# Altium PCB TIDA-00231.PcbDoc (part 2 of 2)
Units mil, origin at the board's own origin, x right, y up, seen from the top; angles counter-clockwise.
Board outline 3780 x 2000 mil, 4 copper layers (Top Layer, L2_GND-PLANE, L3_PWR-PLANE, Bottom Layer), stack 90 mil thick; 180 components, 82 nets, 468 pads, 188 vias.
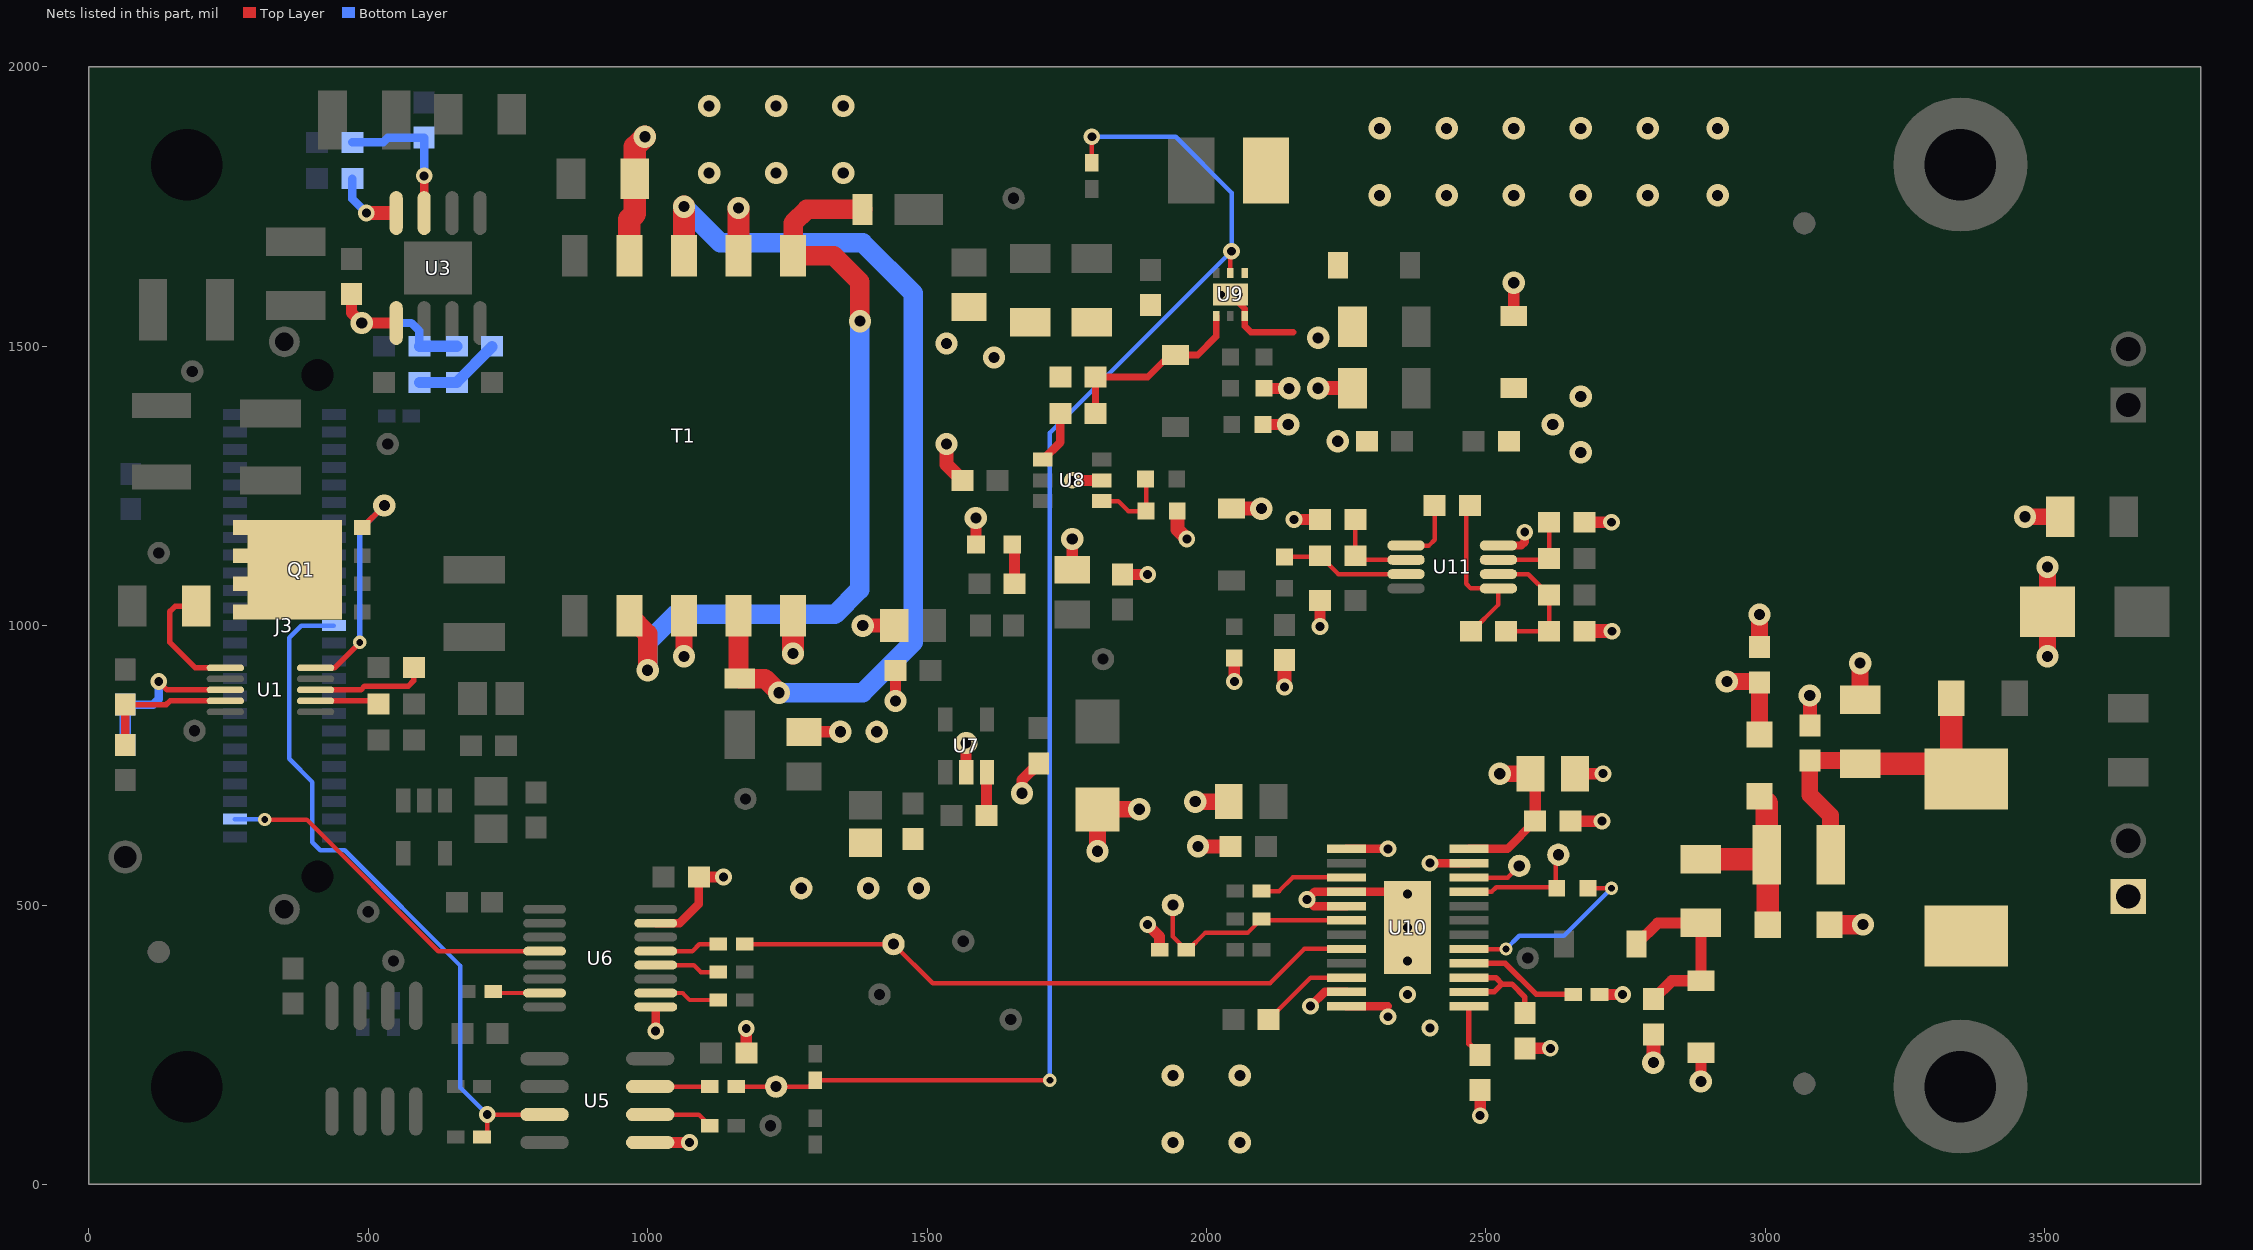
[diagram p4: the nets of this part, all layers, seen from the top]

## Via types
v1: diameter 40, hole 20, Top Layer to Bottom Layer, tented both sides, 92 vias
v2: diameter 30, hole 16, Top Layer to Bottom Layer, tented both sides, 74 vias
v3: diameter 24, hole 12, Top Layer to Bottom Layer, tented both sides, 14 vias
v4: diameter 26, hole 12, Top Layer to Bottom Layer, tented both sides, 4 vias
v5: diameter 25.98, hole 12, Top Layer to Bottom Layer, tented both sides, 4 vias

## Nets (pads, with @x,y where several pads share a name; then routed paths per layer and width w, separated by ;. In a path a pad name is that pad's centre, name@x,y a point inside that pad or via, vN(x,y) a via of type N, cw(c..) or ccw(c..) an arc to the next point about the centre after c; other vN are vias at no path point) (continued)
NetC44_2: C44.2 U10.17 | length 342.4
  Top Layer w8: U10.17@2469.7,421.2 v3(2536.2,421.2) ; C44.2@2683,530 v3(2725,530)
  Bottom Layer w8: v3(2536.2,421.2) 2560,445 2640,445 v3(2725,530)
NetC45_2: C45.2 U10.14 U10.15 | length 208.7
  Top Layer w10: U10.14@2469.7,344.4 2515,344.4 2528.94,358.34 ; U10.15@2469.7,370 2517.88,370 2528.94,358.94 2528.94,358.34 ; C45.2@2570,306.5 2570,335 2546.66,358.34 2528.94,358.34
NetC46_1: C46.1 D9.1 D11.1 R37.2 | length 332.8
  Top Layer w20: D9.1@2770,430 2807.91,467.91 R37.2@2885,467.91 D11.1@2885,364.47 2832.97,364.47 C46.1@2800,331.5
NetC48_1: C48.1 C49.1 D13.1 F1.1 R38.1 | length 595
  Top Layer w30: F1.1@3117.09,590 3117.09,660 3080,697.09 C49.1@3080,758.5 3164.41,758.5 C48.1@3170,752.91
  Top Layer w40: C48.1@3170,752.91 3332.58,752.91 D13.1@3332.91,752.58 ; R38.1@3332.91,870 D13.1@3332.91,752.58 ; D13.1@3360,725.49 D13.1@3332.91,752.58
NetC52_1: C52.1 C53.1 R39.1 | length 156.1
  Bottom Layer w20: C53.1@591.5,1435 R39.1@658.5,1435 ; R39.1@658.5,1436.16 C52.1@721.5,1499.15
NetC52_2: C52.2 R4.2 R41.1 U3.5 | length 324.4
  Top Layer w20: R4.2@470,1593.5 470,1560 v1(488.43,1541.57) ; v1(488.43,1541.57) U3.5@550,1541.57
  Bottom Layer w15: v1(488.43,1541.57) 577.19,1541.57 591.5,1527.27 R41.1@591.5,1500
  Bottom Layer w20: R41.1@591.5,1500 C52.2@658.5,1500
NetC55_1: C55.1 D5.2 R19.1 U9.1 | length 347.8
  Top Layer w12: R19.1@1801.5,1380 C55.1@1801.5,1445 1895,1445 1934.47,1484.47 D5.2@1945,1484.47 1984.47,1484.47 2017.46,1517.46 U9.1@2017.46,1554.3
NetD1_2: D1.2 T1.3 T1.7 | length 1658.6
  Top Layer w20: D1.2@1162.64,907.56 D1.2@1165,905.2
  Top Layer w35: D1.2@1162.64,907.56 T1.7@1162.64,1017.95 ; D1.2@1165,905.2 1209.8,905.2 v1(1235,880)
  Top Layer w40: T1.3@1065,1662.05 v1(1065,1750)
  Bottom Layer w35: v1(1065,1750) 1130,1685 1385,1685 1475,1595 1475,970 1385,880 v1(1235,880)
NetD2_2: D2.2 T1.5 T1.9 | length 1463
  Top Layer w35: T1.9@967.36,1017.95 1000,985.32 v1(1000,920) ; v1(1380,1545) 1380,1615 1332.95,1662.05 T1.5@1260.28,1662.05 1260.28,1720.28 1285,1745 D2.2@1384.8,1745
  Bottom Layer w35: v1(1000,920) 1000,970 1050,1020 1335,1020 1379.5,1064.5 1379.5,1209.5 1380,1210 v1(1380,1545)
NetD3_2: D3.2 R18.1 | length 71.7
  Top Layer w20: D3.2@1652.48,1145 1656.5,1140.98 R18.1@1656.5,1075
NetD7_2: D7.2 L2.2 U9.4
NetD10_1: D10.1 D12.2 F1.2 R37.1 | length 357.2
  Top Layer w40: R37.1@2885,582.09 2995,582.09 F1.2@3002.91,590 ; D12.2@2990,694.88 3002.91,681.97 F1.2@3002.91,590 ; D10.1@3004.88,465 3004.88,588.03 F1.2@3002.91,590
NetQ1_4: Q1.4 U1.10 | length 417.2
  Top Layer w10: U1.10@405.71,924.37 439.37,924.37 v3(485,970) ; Q1.4@489.3,1175.49 v1(528.81,1215)
  Bottom Layer w10: v3(485,970) 485,1171.19 v1(528.81,1215)
NetQ1_5: Q1.5 Q1.6 Q1.7 Q1.8 Q1.9 R3.2 U1.1 | length 224.6
  Top Layer w10: R3.2@192.09,1035 154.68,1035 145,1025.32 145,970 190.63,924.37 U1.1@244.29,924.37
NetR1_1: R1.1 R2.2 U1.4 | length 254.1
  Top Layer w10: R1.1@65,858.5 138.5,858.5 145.32,865.32 U1.4@244.29,865.32
  Top Layer w15: R2.2@65,786.5 R1.1@65,858.5
NetR5_1: R5.1 U1.8 | length 206.1
  Top Layer w10: U1.8@405.71,885 486.73,885 493.43,891.7 571.7,891.7 581.5,901.5 R5.1@581.5,925
NetR6_2: R6.2 U1.7 | length 115
  Top Layer w10: U1.7@405.71,865.32 513.19,865.32 R6.2@518.5,860
NetR9_2: R9.2 U6.7 | length 93
  Top Layer w8: R9.2@723.62,345 726.12,342.5 U6.7@815.59,342.5
NetR10_1: R10.1 U5.7 | length 106.9
  Top Layer w8: U5.7@1004.49,175 R10.1@1111.38,175
NetR11_1: R11.1 U5.6 | length 115.2
  Top Layer w8: U5.6@1004.49,125 1091.38,125 R11.1@1111.38,105
NetR12_1: R12.1 U6.13 | length 117.1
  Top Layer w8: U6.13@1014.41,417.5 1080.13,417.5 1092.63,430 R12.1@1126.38,430
NetR13_1: R13.1 U6.12 | length 117.1
  Top Layer w8: U6.12@1014.41,392.5 1082.5,392.5 1095,380 R13.1@1126.38,380
NetR14_1: R14.1 U6.10 | length 117.1
  Top Layer w8: U6.10@1014.41,342.5 1062.5,342.5 1075,330 R14.1@1126.38,330
NetR17_1: R17.1 U7.3 | length 76
  Top Layer w20: U7.3@1605,735.35 1606.5,733.86 R17.1@1606.5,660
NetR19_2: R19.2 U8.4 | length 95.8
  Top Layer w15: U8.4@1707.5,1297 1738.5,1328 R19.2@1738.5,1380
NetR20_1: R20.1 R21.2 U8.1 | length 144.8
  Top Layer w8: U8.1@1812.5,1223 1842,1223 1860,1205 R21.2@1892,1205 1892,1261.46 R20.1@1891,1262.46
NetR23_1: R23.1 R28.1 TP18.1 U10.6 | length 400.7
  Top Layer w8: TP18.1@1940,500 1940,443.62 R23.1@1963.62,420 1967.56,420 1997.56,450 2073.62,450 R28.1@2098.62,475 2101.12,472.5 U10.6@2250.7,472.5
NetR26_2: R26.2 U10.10 | length 170.3
  Top Layer w8: R26.2@2111.5,295 2186.6,370.1 U10.10@2250.7,370.1
NetR27_1: R27.1 U10.3 | length 162.1
  Top Layer w8: R27.1@2098.62,525 2130,525 2154.3,549.3 U10.3@2250.7,549.3
NetR30_2: R30.2 R32.1 R48.2 U11.2 | length 248.2
  Top Layer w8: U11.2@2522.68,1092.2 2576.3,1092.2 R48.2@2613.5,1055 R30.2@2613.5,990 R32.1@2536.5,990
NetR31_1: R31.1 R36.2 U11.7 | length 230.1
  Top Layer w8: R31.1@2140,1123 2205.5,1123 2236.3,1092.2 U11.7@2357.32,1092.2
NetR32_2: R32.2 R49.1 U11.1 | length 301.7
  Top Layer w8: R49.1@2471.5,1215 2465,1208.5 2465,1075 2473.39,1066.61 U11.1@2522.68,1066.61 2522.68,1037.68 2475,990 R32.2@2473.5,990
NetR33_1: R33.1 U10.13 | length 95.7
  Top Layer w10: U10.13@2469.7,318.8 2469.7,251.8 R33.1@2490,231.5
NetR34_1: R34.1 U10.16 | length 209.7
  Top Layer w10: U10.16@2469.7,395.6 2534.86,395.6 2590.46,340 R34.1@2656.38,340
NetR35_2: R35.2 R36.1 U11.6 | length 158.8
  Top Layer w8: R35.2@2266.5,1190 R36.1@2266.5,1125 2273.7,1117.8 U11.6@2357.32,1117.8
NetR40_2: R40.2 R44.1 U3.3 | length 399.1
  Top Layer w15: U3.3@600,1738.43 v2(600,1805)
  Bottom Layer w15: v2(600,1805) R40.2@600,1873.5 ; 526.5,1865 R44.1@471.5,1865 526.5,1865 ; 526.5,1865 535,1873.5 ; 526.5,1865 535,1873.5 ; 535,1873.5 R40.2@600,1873.5 ; 535,1873.5 R40.2@600,1873.5
NetR45_1: R45.1 U3.4 | length 125.4
  Top Layer w25: v2(496.57,1738.43) U3.4@550,1738.43
  Bottom Layer w15: R45.1@471.5,1800 471.5,1763.5 v2(496.57,1738.43)
NetR46_1: R46.1 R47.2 U1.3 | length 293.2
  Top Layer w10: v2(125,900) 140,885 U1.3@244.29,885
  Bottom Layer w15: R46.1@65,858.5 115,858.5 125,868.5 v2(125,900)
  Bottom Layer w20: R47.2@65,786.5 R46.1@65,858.5
NetR49_2: R49.2 U11.5 | length 116.9
  Top Layer w8: U11.5@2357.32,1143.39 2398.39,1143.39 2408.5,1153.5 R49.2@2408.5,1215
NetR50_2: R50.2 R51.1 U11.3 | length 156.7
  Top Layer w8: U11.3@2522.68,1117.8 2611.3,1117.8 R50.2@2613.5,1120 R51.1@2613.5,1185
NetTP20_1: TP20.1 U10.22 | length 98.9
  Top Layer w8: U10.22@2469.7,549.2 2539.2,549.2 TP20.1@2560,570
PS_EN: R10.2 R15.1 R22.1 TP8.1 U9.5 | length 2666.9
  Top Layer w8: R10.2@1158.62,175 1288.62,175 R15.1@1300,186.38 v3(1720,186.38) ; R22.1@1795,1828.62 v2(1795,1875) ; U9.5@2043.05,1631.07 2043.05,1668.05 v2(2045,1670)
  Bottom Layer w8: v3(1720,186.38) 1720,1345 v2(2045,1670) 2045,1775 1945,1875 v2(1795,1875)
RCLK: J3.26 R8.1 U5.3 | length 1261.4
  Top Layer w8: R8.1@703.62,85 713,94.38 v2(713,125) U5.3@815.51,125
  Bottom Layer w8: J3.26@438.58,1000 380,1000 358.47,978.47 358.47,761.53 400,720 400,612.16 414.08,598.08 457.92,598.08 665,391 665,173 v2(713,125)
SCLK: J3.3 U6.4 | length 651.9
  Top Layer w8: v3(315,653) 390,653 625.5,417.5 U6.4@815.59,417.5
  Bottom Layer w8: J3.3@261.42,653.54 314.46,653.54 v3(315,653)
SCLK_ISO: R12.2 TP13.1 U10.8 | length 1131.5
  Top Layer w8: R12.2@1173.62,430 TP13.1@1440,430 1510,360 2114,360 2175.3,421.3 U10.8@2250.7,421.3
SGND: C17.2 C18.2 C19.2 C20.2 C21.1 C22.2 C23.2 C24.2 C25.2 C26.2 C27.2 C28.2 C29.2 C30.2 C31.2 C32.2 C33.1 C34.1 C35.2 C36.2 C37.2 C38.2 C39.2 C40.2 C41.2 C42.1 C43.2 C45.1 C46.2 C47.2 C48.2 C49.2 C50.1 C55.2 D3.1 D4.2 D6.2 D8.2 D10.2 D11.2 D13.2 D14.1 J2.1 R21.1 R23.2 R24.1 R30.1 R33.2 R34.2 R35.1 R51.2 T1.2 T1.4 T1.6 T1.8 TP11.1 TP14.1 U5.5 U6.9 U6.15 U7.2 U8.2 U9.3 U9.7 U10.1 U10.4 U10.5 U10.11 U10.12 U10.23 U10.25 U11.4 | length 3926.3
  Top Layer w12: U9.7@2043.05,1592.68 2068.64,1567.09 U9.3@2068.64,1554.3 2068.64,1536.36 2080,1525 2155,1525
  Top Layer w15: v2(1014.41,274.41) U6.9@1014.41,317.5 ; U6.15@1014.41,467.5 1057.5,467.5 1091.5,501.5 C18.2@1091.5,550 ; v2(2186.2,318.9) 2211.8,344.5 U10.11@2250.7,344.5 ; U10.12@2250.7,318.9 2325,318.9 ; U10.5@2250.7,498.1 2191.9,498.1 v2(2180,510) 2193.7,523.7 U10.4@2250.7,523.7 2346.3,523.7 2360,510 v2(2360,459.9) ; U10.1@2250.7,600.5 v2(2325,600.5) ; v2(2400,574.8) U10.23@2469.7,574.8 ; U11.4@2522.68,1143.39 2563.39,1143.39 2569.82,1149.82 v2(2569.82,1167.32)
  Top Layer w20: U5.5@1004.49,75 v2(1075,75) ; C18.2@1091.5,550 v2(1136,550) ; C19.2@1176.5,235 v2(1176.5,279) ; C21.1@1280,810 v1(1345,810) ; v1(1443.5,865) C24.2@1443.5,920 ; U7.2@1570,737.76 v1(1570,790) ; D3.1@1587.52,1145 v1(1587.52,1192.52) ; v1(1670,700) 1670,723.5 C29.2@1700,753.5 ; C30.2@1760,1100 v1(1760,1155) ; v2(1760,1260) U8.2@1812.5,1260 ; C32.2@1850,1091.5 v2(1895,1091.5) ; v2(1895,465) 1916.38,443.62 R23.2@1916.38,420 ; v2(2050,900) R24.1@2050,942 ; C35.2@2101.54,1360 v1(2146.54,1360) ; C36.2@2103.05,1424.68 v1(2148.05,1424.68) ; v2(2157.01,1190) R35.1@2203.5,1190 ; v2(2203.5,998.5) C38.2@2203.5,1045 ; v2(2490,123) R33.2@2490,168.5 ; D8.2@2550,1554.47 v1(2550,1613.54) ; C45.1@2570,243.5 v2(2615.5,243.5) ; C43.2@2651.5,650 v2(2708,650) ; C42.1@2660,735 v2(2710,735) ; R51.2@2676.5,1185 v2(2725,1185) ; R34.2@2703.62,340 v2(2745,340) ; v1(2885,184.04) D11.2@2885,235.53
  Top Layer w25: v1(1385,1000) C23.2@1441.54,1000 ; v1(1535,1325) 1535,1288.5 C26.2@1563.5,1260 ; R21.1@1948,1205 1948,1172 v2(1965,1155) ; v1(1985,605) C34.1@2043.5,605 ; D6.2@2045,1209.47 v1(2098.5,1209.47) ; v2(2140,890) C37.2@2140,938.5 ; v1(2200,1425) C40.2@2261.46,1425 ; R30.1@2676.5,990 v2(2726,990) ; v1(2800,217.97) C46.2@2800,268.5 ; C49.2@3080,821.5 v1(3080,875)
  Top Layer w30: v1(1065,945) T1.8@1065,1017.95 ; v1(1805,596.26) D4.2@1805,671.26 v1(1880,671.26) ; v1(1980,685) C33.1@2040,685 ; C47.2@2990,961.5 v1(2990,1020) ; C48.2@3170,867.09 v1(3170,932.91) ; v1(3465,1195) C50.1@3527.91,1195 ; v1(3505.35,945) D14.1@3505.35,1025 v1(3505.35,1105)
  Top Layer w35: D10.2@3115.12,465 v1(3175.12,465)
  Top Layer w40: T1.2@967.36,1662.05 967.36,1727.36 977.09,1737.09 C17.2@977.09,1800 977.09,1857.09 v1(995,1875) ; T1.4@1162.64,1662.05 v1(1162.64,1747.36) ; v1(1260.28,950) T1.6@1260.28,1017.95
  other v1: 1940,75 2060,75 1940,195 2060,195 1395,530 1485,530 2235,1330 1620,1480 1535,1505 2200,1515 2310,1770 2430,1770 2550,1770 2670,1770 2790,1770 2915,1770 1110,1810 1230,1810 1350,1810 2310,1890 2430,1890 2550,1890 2670,1890 2790,1890 2915,1890 1110,1930 1230,1930 1350,1930
  other v2: 2400.3,280 2325,300 2360,339.7 2360,399.8 2360,520
  other v3: 2027.3,1592.68 2058.8,1592.68
VBOOST_OUT: C42.2 C43.1 C47.1 D8.1 D12.1 FB2.2 U10.24 | length 416.2
  Top Layer w15: U10.24@2469.7,600.5 2539,600.5 C43.1@2588.5,650
  Top Layer w20: C42.2@2580,735 2588.5,726.5 C43.1@2588.5,650
  Top Layer w30: v1(2525,735) C42.2@2580,735 ; v1(2931.5,900) C47.1@2980,900 ; D12.1@2990,813.62 C47.1@2990,898.5
  other v1: 2670,1310 2620,1360 2670,1410
VOUT0_0: C44.1 TP22.1 U10.21 | length 218.9
  Top Layer w8: U10.21@2469.7,523.6 2510.4,523.6 2518.8,532 2625,532 2625,585 TP22.1@2630,590
pads on no net: FID1.1 FID2.1 FID3.1 FID4.1 FID5.1 FID6.1 H1.1 H2.1 J3.8 J3.9 J3.13 J3.14 J3.15 J3.17 J3.18 J3.19 J3.20 J3.21 J3.22 J3.23 J3.24 J3.25 J3.27 J3.28 J3.29 J3.30 J3.31 J3.32 J3.33 J3.34 J3.43 J3.44 J3.45 J3.46 J3.47 J3.48 J3.49 J3.MH1 J3.MH2 J3.MH3 J3.MH4 MH1.1 MH2.1 U4.3 U4.4
copper on no net: | length 4560
  Top Layer w8: 3600,140 3700,140 ; 3600,220 3700,220 ; 3600,300 3700,300 ; 3600,60 3600,380 3700,380 3700,60 3600,60
  L2_GND-PLANE w8: 3600,140 3700,140 ; 3600,220 3700,220 ; 3600,300 3700,300 ; 3600,60 3700,60 3700,380 3600,380 3600,60
  L3_PWR-PLANE w8: 3600,140 3700,140 ; 3600,220 3700,220 ; 3600,300 3700,300 ; 3600,60 3600,380 3700,380 3700,60 3600,60
  Bottom Layer w8: 3600,140 3700,140 ; 3600,220 3700,220 ; 3600,300 3700,300 ; 3600,60 3600,380 3700,380 3700,60 3600,60

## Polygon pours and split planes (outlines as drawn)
9.3V_NON_ISO on Bottom Layer "Top Layer-No Net" (hatched 90Degree grid 5 track 8, remove dead copper, pour order 61): 680,800 620,800 605,815 605,1020 585,1040 585,1215 495,1305 495,1370 505,1380 540,1380 545,1375 545,1340 645,1240 645,1035 690,990 690,810
GND on Bottom Layer "Top Layer-No Net" (hatched 90Degree grid 5 track 8, remove dead copper, pour order 64): 820,45 102.76,45 35,112.76 35,735 45,745 150,745 240,835 240,1100 255,1115 480,1115 503.81,1190 520,1225 220,1225 170,1275 50,1275 25,1300 25,1735 250,1960 870,1960 880,1950 880,1665 850,1635 785,1635 775,1625 775,1610 715,1550 610,1550 585,1575 470,1575 445,1550 445,1490 470,1465 470.08,1255 470,1240 470.08,1225 555,1225 570,1210 570,780 585,765 695,765 725,795 725,1025 675,1075 675,1245 685,1255 685,1350 710,1375 765,1375 785,1355 785,1055 800,1040 870,1040 885,1025 885,990 875,980 840,980 830,970 830,55
+24VDC on Bottom Layer "Bottom Layer-No Net 2" (solid, remove dead copper, pour order 57): 465,1195 470,1190 470,1150 465,1145 215,1145 195,1125 195,915 180,900 40,900 25,915 25,1220 35,1230 110,1230 145,1195
GND_EARTH on Bottom Layer "Bottom Layer-No Net" (solid, remove dead copper, pour order 69): 3740,830 3620,830 3620,1660 3635,1675 3730,1675 3745,1660 3745,835
SGND on Bottom Layer "Bottom Layer-No Net" (solid, remove dead copper, pour order 74): 978.35,975 978.35,41.65 990,30 3735,30 3745,40 3745,755 3735,765 3595,765 3580,780 3580,1905 3520,1965 950,1965 945,1960 945,1635 955,1625 1325,1625 1335,1615 1335,1065 1320,1050 950,1050 945,1045 945,980 973.35,980
VBOOST_OUT on L3_PWR-PLANE "Bottom Layer-No Net" (solid, remove dead copper, pour order 70): 3555,1610 3555,780 3570,765 3730,765 3745,750 3745,405 3555,405 3495,345 3225,345 3170,290 3170,60 3140,30 2470,30 2445,55 2445,1615 2480,1650 3515,1650
+5V_ISO on L3_PWR-PLANE "Bottom Layer-No Net" (solid, remove dead copper, pour order 72): 2415,50 2415,1530 2390,1555 1515,1555 1500,1540 1500,730 1475,705 1060,705 980,625 978.35,41.65 990,30 2395,30
+3.3V_NON_ISO on L3_PWR-PLANE "Top Layer-No Net" (hatched 90Degree grid 5 track 8, remove dead copper, pour order 62): 830,665 845,650 845,45 835,35 395,35 365,65 365,320 330,355 95,355 35,415 35,810 60,835 395,835 565,665
GND on L2_GND-PLANE "Top Layer-No Net" (hatched 90Degree grid 5 track 8, remove dead copper, pour order 63): 835,35 99.13,35 32,102.14 30,104.13 30,465 30,1930 65,1965 125,1965 388,1965 860,1965 874,1951 885,1940 885,1875 885,1650 870,1635 810,1635 795,1635 780,1620 780,1600 780,1055 795,1040 853,1040 871,1040 880,1031 880,985 875,980 855,980 850,980 840,970 840,930 840,40 835,35
SGND on L2_GND-PLANE "Bottom Layer-No Net" (solid, remove dead copper, pour order 73): 978.35,975 978.35,41.65 990,30 3735,30 3745,40 3745,755 3735,765 3595,765 3580,780 3580,1905 3520,1965 950,1965 945,1960 945,1635 955,1625 1325,1625 1335,1615 1335,1065 1320,1050 950,1050 945,1045 945,980 973.35,980
NetD7_2 on Top Layer "Bottom Layer-No Net" (solid, remove dead copper, pour order 47): 2060,1625 2250,1625 2250,1675 2155,1675 2150,1680 2150,1920 2145,1925 2065,1925 2060,1920
+12V_ISO on Top Layer "Bottom Layer-No Net" (solid, remove dead copper, pour order 40): 1450,1790 1450,1650 1475,1625 2025,1625 2025,1915 2020,1920 1930,1920 1925,1915 1925,1720 1900,1695 1845,1695 1835,1705 1835,1780 1820,1795 1455,1795
VBOOST_OUT on Top Layer "Bottom Layer-No Net" (solid, remove dead copper, pour order 49): 2700,1270 2725,1295 2725,1425 2695,1455 2535,1455 2530,1450 2530,1280 2540,1270
NetC39_1 on Top Layer "Bottom Layer-No Net" (solid, remove dead copper, pour order 48): 2340,1255 2340,1710 2355,1725 2420,1725 2435,1710 2435,1375 2445,1365 2495,1365 2500,1360 2500,1265 2485,1250 2345,1250
SGND on Top Layer "Bottom Layer-No Net" (solid, remove dead copper, pour order 66): 2090,1315 2090,1435 2125,1435 2135,1445 2135,1515 2125,1525 2080,1525 2065,1540 2065,1570 2060,1575 2005,1575 1960,1530 1870,1530 1835,1495 1760,1495 1750,1485 1750,1425 1555,1425 1515,1465 1515,1585 1525,1595 1620,1595 1655,1570 1840,1570 1865,1595 1935,1595 1955,1615 2100,1615 2125,1590 2280,1590 2290,1580 2290,1385 2305,1370 2305,1300 2105,1300
NetC1_2 on Top Layer "Bottom Layer-No Net 3" (hatched 90Degree grid 5 track 8, remove dead copper, pour order 58): 75,1370 75,1420 130,1420 210,1500 210,1840 470,1840 485,1855 485,1950 500,1965 650,1965 660,1955 660,1705 655,1700 635,1700 630,1705 630,1820 615,1835 575,1835 565,1825 565,1805 555,1795 505,1795 420,1710 420,1650 410,1640 320,1640 290,1610 290,1475 185,1370
NetC10_2 on Top Layer "Top Layer-No Net" (hatched 90Degree grid 5 track 8, remove dead copper, pour order 55): 785,1400 780,1395 715,1395 710,1400 710,1480 695,1495 695,1555 700,1560 725,1560 735,1570 735,1660 775,1700 870,1700 875,1695 875,1635 860,1620 796.22,1620 785,1608.78
GND on Top Layer "Top Layer-No Net 7" (hatched 90Degree grid 5 track 8, remove dead copper, pour order 54): 450,1670 450,1640 455,1635 495,1635 535,1595 700,1595 710,1605 710,1665 785,1740 785,1900 800,1915 860,1915 870,1925 870,1955 860,1965 705,1965 695,1955 695,1695 680,1680 460,1680
+24VDC on Top Layer "Top Layer-No Net 10" (solid, remove dead copper, pour order 59): 25,1200 25,900 85,900 85,1045 100,1045 100,1085 110,1095 200,1095 200,1200
NetQ1_5 on Top Layer "Top Layer-No Net 11" (solid, remove dead copper, pour order 60): 170,1070 170,1000 455,1000 455,1190 260,1190 260,1070
GND on Top Layer "Top Layer-No Net" (hatched 90Degree grid 5 track 8, remove dead copper, pour order 65): 30,725 126,725 135,716 140,711 140,666 140,468 188,420 198,410 318,410 328,410 333,405 333,344 320,331 264,275 150,275 70,275 30,315 20,325 20,670 20,715 30,725
+24VDC_LIMIT on Top Layer "Top Layer-No Net 9" (hatched 90Degree grid 5 track 8, remove dead copper, pour order 56): 505,980 505,925 535,925 535,950 540,955 560,955 625,1020 625,1285 620,1290 70,1290 70,1240 475,1240 480,1235 480,1005
GND on Top Layer "Top Layer-No Net" (hatched 90Degree grid 5 track 8, remove dead copper, pour order 52): 835,680 735,680 735,893.1 751.9,910 830,910 845,895 845,690
+3.3V_NON_ISO on Top Layer "Top Layer-No Net" (hatched 90Degree grid 5 track 8, remove dead copper, pour order 53): 660,610 700,650 830,650 840,640 840,540 835,535 775,535 765,545 765,580 755,590 690,590 675,575 620,575 615,580 615,605 620,610
9.3V_NON_ISO on Top Layer "Top Layer-No Net" (hatched 90Degree grid 5 track 8, remove dead copper, pour order 51): 880,1040 815,1040 780,1005 645,1005 625,985 625,670 635,660 660,660 670,670 670,730 700,760 700,910 715,925 760,925 835,1000 875,1000 880,1005
GND on Top Layer "Top Layer-No Net 1" (hatched 90Degree grid 5 track 10, remove dead copper, pour order 50): 325,1600 420,1600 430,1590 430,1560 450,1540 460,1530 535,1455 535,1405 495,1365 405,1365 290,1365 285,1370 285,1415 285,1435 315,1465 320,1470 320,1505 320,1595 325,1600
GND on Top Layer "Bottom Layer-No Net" (solid, remove dead copper, pour order 67): 455,1875 350,1875 345,1880 345,1965 350,1970 450,1970 455,1965
SGND on Top Layer "Bottom Layer-No Net" (solid, remove dead copper, pour order 71): 2305,289.9 2305,645 2310,650 2370,650 2405,650 2410,650 2415,645 2420,640 2420,535 2420,270 2415,265 2350,265 2310,265 2305,270 2305,289.9
GND_EARTH on Top Layer "Bottom Layer-No Net" (solid, remove dead copper, pour order 68): 3740,830 3635,830 3620,845 3620,1660 3635,1675 3730,1675 3745,1660 3745,835
GND on Top Layer "Bottom Layer-No Net" (solid, remove dead copper, pour order 42): 140,1455 40,1455 30,1465 30,1475 30,1625 35,1630 100,1630 130,1630 140,1620 140,1585 140,1455
+6V_ISO on Top Layer "Bottom Layer-No Net" (solid, remove dead copper, pour order 45): 1120,830 1200,830 1215,815 1215,770 1230,755 1545,755 1545,700 1560,685 1560,640 1520,640 1505,655 1140,655 1115,680 1115,820
SGND on Top Layer "Bottom Layer-No Net" (solid, remove dead copper, pour order 43): 1230,625 1490,625 1515,600 1515,520 1500,505 1220,505 1210,515 1210,605
NetC23_1 on Top Layer "Bottom Layer-No Net" (solid, remove dead copper, pour order 39): 1545,820 1535,810 1495,810 1485,820 1485,1085 1500,1100 1615,1100 1615,980 1605,970 1550,970 1545,965
+5V_ISO on Top Layer "Bottom Layer-No Net" (solid, remove dead copper, pour order 46): 1645,1025 1645,960 1660,945 1750,945 1765,930 1765,805 1780,790 1895,790 1910,805 1910,1030 1890,1050 1730,1050 1720,1040 1660,1040
SGND on Top Layer "Bottom Layer-No Net" (solid, remove dead copper, pour order 38): 3620,550 3680,550 3685,545 3685,485 3620,420 3505,420 3470,385 3280,385 3280,505 3575,505
AOUT0 on Top Layer "Bottom Layer-No Net" (solid, remove dead copper, pour order 41): 3685,595 3685,760 3610,760 3590,760 3525,825 3475,875 3475,895 3475,900 3470,905 3435,905 3420,905 3415,900 3415,840 3510,745 3615,640 3615,590 3625,580 3635,580 3670,580 3685,595
NetC48_1 on Top Layer "Bottom Layer-No Net" (solid, remove dead copper, pour order 44): 3280,665 3235,710 3140,710 3130,720 3130,780 3135,785 3210,785 3285,860 3285,895 3300,910 3350,910 3360,900 3360,815 3390,785 3435,785 3435,665

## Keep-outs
Keep-Out Layer:
  circle w4: c409.06,551.18 r32
  circle w4: c409.06,1448.82 r35
  circle w8: c3349.53,175 r135
  circle w8: c3349.53,1825 r135
  pour cut-out: 3560,20 3760,20 3760,400 3560,400
  text ".Layer_Name" at 577,-858.49 h60

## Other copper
Top Layer:
  pour cut-out: 513,1187 513,1155.14 505.86,1148 476,1148 472,1152 472,1178 481,1187
  region net +12V_ISO: 2014.41,1705 2014.41,1650.59 2020,1645 1990,1645 1990,1705
  region net NetC45_2: 2517.88,370 2517.88,352.72 2520.6,350 2528.94,358.34 2528.94,358.94
  text "1" at 3671,93 h50 r90
  text ".Layer_Name" at 577,-858.49 h60
L2_GND-PLANE:
  text "2" at 3674,164 h50 r90
  text ".Layer_Name" at 612,-866 h60
L3_PWR-PLANE:
  text "3" at 3674,244 h50 r90
  text ".Layer_Name" at 640,-860 h60
Bottom Layer:
  pour cut-out: 2639.61,1010 2639.61,1060 2731.02,1151.41 2758.2,1151.41 2770,1139.61 2770,1070.39 2709.61,1010
  pour cut-out: 2650,1010 2650,615 2645,610 2670,610 2670,1010
  pour cut-out: 2720,610 2685,645 2665,645 2665,620 2675,610
  pour cut-out: 505,1220 470,1220 470,1270 500,1270 510,1260 510,1225
  pour cut-out: 505,1750 505,1845 500,1850 385,1850 378,1843 378,1750.07 383.07,1745 500,1745
  pour cut-out: 592,1834 481,1834 479,1836 479,1966 489,1976 573,1976 574,1975 574,1889 592,1871
  pour cut-out: 327.83,600.2 227.8,600.2 223,605 223,673 235,685 345,685 360,670 360,632.37
  pour cut-out: 530,295 505,295 505,400 530,400 530,390 535,385 535,300
  pour cut-out: 508.88,240.88 471.65,242 466.19,247.46 466.19,403.84 470.35,408 535,408 541,402 541,273
  pour cut-out: 568.81,381.19 560,390 530,390 530,300 532.5,297.5 535.87,300.87 568.81,300.87
  pour cut-out: 383.83,605 357.33,578.5 357.33,531 385.21,503.12 437.12,503.12 460,526 460,596 451,605
  pour cut-out: 1430,1620 1455,1590 1455,1510 1360,1510 1360,1065 1335,1040 1300,1040 1290,1050 1290,1615 1295,1620
  pour cut-out: 1420,1620 1365,1675 1060,1675 1055,1670 1055,1620 1320,1620 1345,1595 1410,1595 1420,1605
  pour cut-out: 1055,1670 1055,1725 1060,1730 1080,1730 1120,1690 1120,1670
  pour cut-out: 2710,620 2720,610 2720,525 2640,445 2515,445 2505,455 2505,580 2545,620
  text "4" at 3620,325 h50 r270
  text ".Layer_Name" at 577,-858.49 h60
Multi-Layer:
  pour cut-out: 851.18,0 978.35,0 978.35,975 940,975 940,1060 1323.78,1060 1323.78,1620 945,1620 945,2000 890,2000 890,1620 796.22,1620 796.22,1060 895,1060 895,970 851.18,970

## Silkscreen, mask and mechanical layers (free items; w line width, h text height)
Top Overlay:
  circle w8: c2522.68,1035 r10
  circle w10: c530,1036 r10
  circle w11: c669,685 r5
  circle w20: c394,125 r6
  circle w8: c1490.6,741 r11.4
  circle w8: c833.93,257 r7.07
  circle w8: c2018,1523 r5
  lines w6: 25,635 425,635 445,635 465,635 465,720 624,720 624,795 ; 25,636 25,1220 235,1220 ; 408,1240 608,1240 ; 543,1010 543,965 ; 610,965 610,1240 ; 1183,195.5 1203.5,195.5 1231,223 1242,223 ; 1190,495 1760,495 ; 1250,161 1258,153 1341,153 ; 1480,1700 1480,1450 1695.43,1450 ; 1480,1805 1480,1965 2615,1965 2615,1955 2615,1595 2705,1505 2705,1255 ; 1840,1445 1885,1445 1895,1445 1895,1306 1964,1306 2015,1255 2705,1255 ; 1893,1126 1893,1171 ; 1980,1015 1980,830 ; 2000,474 2021,474 ; 2014,1295 2009,1300 2009,1390.64 2019.05,1400.68 ; 2228,914 2228,981 2218,971 2221,971 2239,971 2229,981 ; 2518,645 2561,602 ; 2586,494 2819,494 2819,1103 3305,1103 3509,899 3601,899 ; 2609,325 2639,295 2639,140 3006,140 3006,319 3477,319 3562,404 3760,404 ; 2630,50 1760,50 1760,430 1760,540 1903.21,540 1903.21,735 1980,735 1980,830 ; 2660,590 2670,600 2700,600 ; 2673,380 2605,380 2605,480 2805,480 2805,380 2729,380 ; 543,965 551,973 535,973 543,965 ; 1893,1171 1903,1161 1883,1161 1893,1171 ; 1980,830 2805,830 2805,1255 2705,1255 ; 1675,1188 1844,1188 1844,1332 1675,1332 1675,1188 ; 2200,289.9 2520,289.9 2520,629.9 2200,629.9 2200,289.9
  text "ADAPTIVE PWR" at 1492,1911 h40
  text "SUPPLY" at 1529,1860 h60
  text "TIDA-00231  Rev E1" at 2840,1385 h40
  text "FLY BUCK CONV" at 405,1355 h53
  text "O/P PROTECTION CKT" at 2839,1047 h50
  text "F/B SECTION" at 2385,850 h60
  text "DAC SECTION" at 2135,765 h60
  text "INRUSH CURR" at 108,695 h55
  text "PROTECTION" at 108,645 h55
  text "+5V LDO" at 1535,515 h53
  text "DIG. ISOLATORS" at 1365,50 h53
  text ".Layer_Name" at 577,-858.49 h60
Bottom Overlay:
  circle w10: c207,622 r7.62
  lines w6: 565,1639 565,1574 559,1580 572,1580 566,1574
  text "49" at 218,1360 h50
  text "2" at 506,604 h50
  text "TIDA-00231  Rev E1" at 2460,120 h40
  text ".Layer_Name" at 577,-858.49 h60
Top Paste:
  text ".Layer_Name" at 577,-858.49 h60
Bottom Paste:
  text ".Layer_Name" at 577,-858.49 h60
Top Solder:
  text ".Layer_Name" at 577,-858.49 h60
  text ".Layer_Name" at 577,-858.49 h60
Bottom Solder:
  text ".Layer_Name" at 577,-858.49 h60
Drill Guide:
  text ".Layer_Name" at 577,-858.49 h60
M1 Board Outline:
  the board outline again, w10
  text ".Layer_Name" at 577,-858.49 h60
M2 Board Dimensions:
  rectangle: -0.5,-285.5 124.5,-160.5
  rectangle: 124.5,-410.5 499.5,-285.5
  lines w7: -0.5,-285.5 999.5,-285.5 ; 124.5,-410.5 124.5,-160.5 ; 249.5,-410.5 249.5,-160.5 ; 499.5,-410.5 499.5,-160.5 ; 749.5,-410.5 749.5,-160.5 ; -0.5,-410.5 999.5,-410.5 999.5,-160.5 -0.5,-160.5 -0.5,-410.5
  lines w7.87: 0,25 3780,25 ; 0,1960 3780,1960 ; 50,45 50,2000 ; 1645,1420 1830,1420 1870,1460 1870,1680 2010,1820 2345,1820 2370,1795 2370,960 2415,915 2655,915 2700,870 2700,225 2715,210 2760,210 2775,225 2775,925 2820,970 2880,1030 3045,1030 3150,1030 3245,1125 3475,1125 3490,1110 3745,1110 ; 2615,1230 2710,1230 2725,1245 2725,1805 2745,1825 2805,1825 2825,1805 2825,1130 2845,1110 2908.83,1110 2920,1121.17 2920,1160 ; 2685,1230 2520,1230 2500,1250 2500,1860 2480,1880 1595,1880 1575,1860 1575,1570 1645,1500 1645,1265 1625,1245 1465,1245 1450,1260 1450,1920 1490,1960 3110,1960 3110,1245 3090,1225 3045,1225 3035,1235 3035,1858.07 3013.07,1880 2940,1880 2920,1860 2920,1135 ; 3745,0 3745,2000
  lines w10: -0.5,-475.5 -0.5,-455.5 ; 59.5,-485.5 -0.5,-465.5 ; 59.5,-445.5 -0.5,-465.5 ; 223.58,-465.5 -0.5,-465.5 ; 775.42,-465.5 999.5,-465.5 ; 939.5,-485.5 999.5,-465.5 ; 939.5,-445.5 999.5,-465.5 ; 999.5,-475.5 999.5,-455.5
  text "1000 (mil)" at 233.58,-501.49 h60
  text ".Layer_Name" at 577,-858.49 h60
M3 3D STEP Top:
  text ".Layer_Name" at 577,-858.49 h60
M4 3D STEP Bottom:
  text ".Layer_Name" at 577,-858.49 h60
M5 Assembly Top:
  circle w15: c638,727 r6
  circle w15: c244.29,951.93 r6
  circle w8: c1503,736 r10
  lines w3.94: 293.5,822.01 293.5,947.99 356.5,947.99 356.5,822.01 293.5,822.01
  lines w4: 1935.67,1716.57 2144.33,1716.57 ; 1935.67,1913.43 2144.33,1913.43
  lines w6: 1488,1147 1509,1147 ; 1509,1123 1509,1173 ; 1535,1147 1560,1147 ; 3500.04,947.44 3679.97,947.44 ; 3500.04,1102.56 3679.97,1102.56 ; 1509,1147 1534,1122 1534,1172 1509,1147
  lines w10: -292,-930.17 6308,-930.17 ; -292,-726.83 6310,-726.83 ; -292,-523.5 -292,-1133.5 3713,-1133.5 6310,-1133.5 6310,-523.5 -291.5,-523.5 -291.5,-1133.5 1284,-1133.5 ; 2173,-1133.5 2173,-523.5 ; 3735,-726 3735,-522.67 ; 4280,-726.83 4280,-523.5 ; 4902,-1140 4902,-937.17
  text "L2" at 2019,1785 h30
  text "D14" at 3535,1005 h40
  text "COMPONENTS MARKED 'DNP' SHOULD NOT BE POPULATED." at 1153.5,-318.5 h60
  text "ASSEMBLY VARIANT:" at 1153,-434 h60
  text ".VariantName" at 2189,-434 h60
  text "PCB VIEWED FROM TOP SIDE" at -228.5,-655.67 h60
  text "BOARD #:" at 2248,-655.67 h60
  text "TIDA-00231" at 2793.5,-655.67 h60
  text "SVN REV:" at 4476,-655.67 h60
  text ".VersionControl_RevNumber" at 4982,-655.67 h60
  text "REV: E1" at 3805,-660 h60
  text "IGNORE ->" at -228.5,-858.49 h60
  text "PLOT NAME =" at -228.5,-1064.34 h60
  text ".plot_File_Name" at 577,-1064.34 h60
  text "GENERATED    :" at 2250,-1064.34 h60
  text ".Print_Date" at 3119.5,-1064.34 h60
  text ".Print_Time" at 3848.5,-1064.34 h60
  text "TEXAS INSTRUMENTS" at 5113,-1064.34 h60
M6 Assembly Bottom:
  circle w20: c212,618 r6
  lines w10: -292.5,-727.33 6309.5,-727.33 ; -290.5,-930.67 6309.5,-930.67 ; 1115.5,-1140.5 1115.5,-937.67 ; 1737.5,-727.33 1737.5,-524 ; 2236,-723 2236,-519.67 ; 3844.5,-1134 3844.5,-524 ; 4733.5,-1134 6309,-1134 6309,-524 -292.5,-524 -292.5,-1134 2304.5,-1134 6309.5,-1134 6309.5,-524
  text "49" at 222,1358 h40
  text "2" at 501,596 h40
  text "COMPONENTS MARKED 'DNP' SHOULD NOT BE POPULATED." at 6102,-318 h60
  text ".VariantName" at 5058,-434 h60
  text "ASSEMBLY VARIANT:" at 6097,-434 h60
  text "REV: E1" at 2173,-655 h60
  text ".VersionControl_RevNumber" at 1035.5,-656.17 h60
  text "SVN REV:" at 1541.5,-656.17 h60
  text "TIDA-00231" at 3224,-656.17 h60
  text "BOARD #:" at 3769.5,-656.17 h60
  text "PCB VIEWED FROM BOTTOM SIDE" at 6246,-656.17 h60
  text "IGNORE ->" at 2547.85,-858.49 h60
  text "TEXAS INSTRUMENTS" at 904.5,-1064.84 h60
  text ".Print_Time" at 2169,-1064.84 h60
  text ".Print_Date" at 2898,-1064.84 h60
  text "GENERATED    :" at 3767.5,-1064.84 h60
  text ".plot_File_Name" at 5440.5,-1064.84 h60
  text "PLOT NAME =" at 6246,-1064.84 h60
M9 Title Sheet:
  drawing of 57 lines, arcs and shapes, not listed
  text "1" at 739.84,8036.5 h70
  text "2" at 3235.5,8036.5 h70
  text "3" at 5724.84,8036.5 h70
  text "4" at 8231.51,8036.5 h70
  text "5" at 10730.5,8036.5 h70
  text "6" at 13235.5,8036.5 h70
  text "A" at -416.5,6893.5 h70
  text "A" at 14383.5,6893.5 h70
  text "B" at -416.5,4513.5 h70
  text "B" at 14383.5,4513.5 h70
  text "C" at -416.5,2138.5 h70
  text "C" at 14383.5,2138.5 h70
  text "PROJECT TITLE:" at 11343.5,277.5 h45
  text ".PRJ_Title" at 11393.5,144.17 h70
  text "DESIGNED FOR:" at 11343.5,-23.5 h45
  text ".PRJ_Customer" at 11393.5,-163.5 h70
  text "D" at -416.5,-231.5 h70
  text "D" at 14383.5,-231.5 h70
  text "FILE NAME:" at 11343.5,-323.5 h45
  text "TIDA-00231" at 11393.5,-443.5 h70
  text "Texas Instruments (TI) and/or its licensors do not warrant the accuracy or completeness of this specification" at 6374,-605.34 h45
  text "ENGINEER:" at 11343.5,-613.5 h45
  text "LAYOUT BY:" at 12848.5,-613.5 h45
  text "or any information contained therein. TI and/or its licensors do not warrant that this design will meet" at 6329.01,-718 h45
  text ".PCB_Layout" at 12860,-760 h40
  text ".PRJ_Engineer" at 11393.5,-768.49 h70
  text "the specifications, will be suitable for your application or fit for any particular purpose, or will operate in" at 6329.01,-830.67 h45
  text "ALTIUM DESIGNER VERSION:" at 12848.5,-923.5 h45
  text "an implementation. TI and/or its licensors do not warrant that the design is production worthy. You should" at 6329.01,-943.33 h45
  text "completely validate and test your design implementation to confirm the system functionality for your application." at 6374,-1056 h45
  text ".print_Scale" at 11393.5,-1056.83 h70
  text ".Application_BuildNumber" at 12899,-1056.83 h70
  text "1" at 739.84,-1263.5 h70
  text "2" at 3235.5,-1263.5 h70
  text "3" at 5724.84,-1263.5 h70
  text "4" at 8231.51,-1263.5 h70
  text "5" at 10730.5,-1263.5 h70
  text "6" at 13235.5,-1263.5 h70
M10 Fab Notes:
  drawing of 228 lines, arcs and shapes, not listed
  text "DESIGN INFORMATION" at 12381.02,6810 h60
  text "(REFER ALSO ARRAY/PANEL PROFILING INFORMATION)" at 12019.46,6648.29 h60
  text "BOARD SIZE" at 11333.46,6644 h60
  text "3780MIL" at 11795.78,6516.18 h60
  text "X" at 12301.46,6516.18 h60
  text "2000MIL" at 12532.78,6516.18 h60
  text "Number of Layers :" at 11736.46,6319 h60
  text "4" at 12831.27,6309 h60
  text "MIN. TRACK WIDTH:" at 11736.46,6180 h60
  text "8" at 12832.7,6180 h60
  text "MIL" at 12987.46,6180 h60
  text "7.87" at 12737,6051 h60
  text "MIN. CLEARANCE:" at 11736.46,6048 h60
  text "MIL" at 12987.46,6048 h60
  text "MIN. VIA PAD SIZE:" at 11736.46,5916 h60
  text "24" at 12802.71,5916 h60
  text "MIL" at 12987.46,5916 h60
  text "0.152mm (6MIL)" at 12431.46,5774.29 h60
  text "EXTERNAL" at 13182,5772 h60
  text "MINIMUM ANNULAR RING" at 11407.23,5770 h60
  text "PER" at 11607.23,5652 h60
  text "IPC-D-275 CLASS 2 LEVEL C" at 11827.23,5652 h60
  text "MIL, HOLES" at 13315.46,5539.71 h60
  text "+/-" at 12923,5539 h60
  text "+/-" at 13777,5539 h60
  text "REGISTRATION TOLERANCES:" at 11407.23,5534 h60
  text "METAL" at 12607,5534 h60
  text "5" at 13183.2,5534 h60
  text "3" at 14016.2,5534 h60
  text "MIL" at 14132.46,5534 h60
  text "MATERIAL:" at 11332.46,5324.54 h60
  text "FR-4 High Tg" at 12318.9,5184.21 h60
  text "X" at 11606.46,5175.64 h60
  text "FR-408" at 11753.46,5175.64 h60
  text "OTHER" at 13241.46,5175.64 h60
  text "63 MIL (1.6mm) +/-10%" at 12073.56,5012.92 h60
  text "THICKNESS:" at 11407.23,5008.64 h60
  text "X" at 11945.4,5008.64 h60
  text "OTHER" at 13358.46,5008.64 h60
  text "TOLERANCE:" at 11407.23,4850.64 h60
  text "X" at 12246.53,4850.64 h60
  text "ANSI IPC-6012 TYPE 3 CLASS 2" at 12433.48,4850.64 h60
  text "OTHER +/-" at 12433.46,4694.64 h60
  text "BOW & TWIST:" at 11407.23,4537.64 h60
  text "X" at 12246.53,4537.64 h60
  text "ANSI IPC-6012 TYPE 3 CLASS 2" at 12433.48,4537.64 h60
  text "OTHER +/-" at 12433.46,4379.13 h60
  text "COPPER THICKNESS (FINISHED):" at 11332.46,4243.64 h60
  text "1.4MIL (1oz)" at 12212.46,4090.92 h60
  text "2MIL (1.4oz)" at 12979.46,4090.92 h60
  text "2.8MIL (2oz)" at 13706.46,4090.92 h60
  text "OUTER:" at 11689.46,4086.64 h60
  text "X" at 12084,4086 h60
  text "1.4MIL (1oz)" at 12212.46,3933.92 h60
  text "2.8MIL (2oz)" at 12979.46,3933.92 h60
  text "N/A" at 13706,3934.29 h60
  text "INNER SIGNAL:" at 11400.38,3929.64 h60
  text "X" at 12085.42,3929.64 h60
  text "DRILLING:" at 11332.46,3790.64 h60
  text "REFERENCE:" at 11407.23,3673.64 h60
  text "X" at 12055.46,3673.64 h60
  text "AS SHOWN" at 12242.46,3673.64 h60
  text "X" at 12956.46,3673.64 h60
  text "NC_DRILL FILES" at 13093.46,3673.64 h60
  text "PTH MIN COPPER THICKNESS:" at 11407.23,3515.64 h60
  text "X" at 12757.46,3515.64 h60
  text "1MIL" at 12894.46,3515.64 h60
  text "OTHER" at 13391.46,3515.64 h60
  text "BOARD FINISH:" at 11332.46,3356.64 h60
  text "SILKSCREEN:" at 11487.68,3238.64 h60
  text "X" at 12436.46,3238.64 h60
  text "TOP" at 12562.46,3238.64 h60
  text "X" at 12946.46,3238.64 h60
  text "BOTTOM" at 13073.46,3238.64 h60
  text "SILKSCREEN COLOR:" at 11486.01,3072.64 h60
  text "X" at 12433.75,3072.64 h60
  text "WHITE" at 12560.79,3072.64 h60
  text "OTHER" at 13071.79,3072.64 h60
  text "SOLDER RESIST COLOR:" at 11592.01,2921.64 h60
  text "GREEN" at 12286.79,2762.44 h60
  text "X" at 12049,2750 h60
  text "BLUE" at 12857,2744 h60
  text "OTHER" at 13306,2740 h60
  text "IMMERSION GOLD (ENIG)" at 12393.46,2553.92 h60
  text "ENEPIG" at 13731,2550.64 h60
  text "SURFACE FINISH:" at 11332.46,2549.64 h60
  text "X" at 12206.51,2549.64 h60
  text "IMM. TIN/SILVER OR EQUIV" at 11662,2392.64 h60
  text "OTHER" at 13093.46,2392.64 h60
  text "ARRAY/PANEL:" at 11332.46,2213.64 h60
  text "CUT AND TRIM PER MECH LAYER 1" at 12393.46,2209.35 h60
  text "N.C. ROUTE" at 12393.46,2057.64 h60
  text "X" at 13072.46,2057.64 h60
  text "V. SCORE" at 13259.46,2057.64 h60
  text "CERTIFICATION:" at 11332.46,1920.64 h60
  text "MATERIALS AND WORKMANSHIP FOR ALL PCBS" at 12057.46,1920.64 h60
  text "TO MEET OR EXCEED THE REQUIREMENTS OF:" at 12057.46,1822.64 h60
  text "X" at 11683.96,1686.13 h60
  text "ANSI IPC-A-600F CLASS ->" at 11822.96,1686.13 h60
  text "X" at 13462.02,1686.13 h60
  text "2" at 13580.96,1686.14 h60
  text "1" at 13265.96,1684.64 h60
  text "3" at 13934.96,1684.64 h60
  text "X" at 11686.02,1526.64 h60
  text "UL 94V-0" at 11822.96,1526.64 h60
  text "X" at 12498.02,1526.64 h60
  text "RoHS" at 12634.96,1526.64 h60
  text "OTHER" at 13279.36,1526.64 h60
  text "PER ORDER" at 13676.42,1526.64 h60
  text "ADDITIONAL REQUIREMENTS:" at 11332.46,1385.64 h60
  text "VIA TENTING:" at 12550,1385 h60
  text "X" at 13316.29,1385.11 h60
  text "YES" at 13099.67,1375.92 h60
  text "NO" at 13464.47,1370.69 h60
  text "MICROSECTION:" at 11407.23,1270.64 h60
  text "YES" at 12312.96,1270.64 h60
  text "IMPEDANCE CONTROL:" at 12576,1261 h60
  text "YES" at 13560,1260 h60
  text "X" at 14102,1253 h60
  text "NO" at 13935.47,1242.69 h60
  text "REQUIRED" at 13174.46,1114.49 h60
  text "BARE BOARD ELEC. TEST:" at 11407.23,1111.64 h60
  text "NONE" at 12712.96,1111.64 h60
  text "X" at 13047.46,1111.64 h60
  text "PER ORDER" at 13766.46,1111.64 h60
  text "MANUFACTURER'S UL:" at 11407.23,954.64 h60
  text "RAIL" at 12572.96,950.35 h60
  text "METAL" at 13064.77,950.35 h60
  text "X" at 13440,950 h60
  text "SILK" at 13576.46,950.35 h60
M11 Gerber Information:
  lines w10: -292,-930.17 6308,-930.17 ; -292,-726.83 6310,-726.83 ; -292,-523.5 -292,-1133.5 3713,-1133.5 6310,-1133.5 6310,-523.5 -291.5,-523.5 -291.5,-1133.5 1284,-1133.5 ; 2173,-1133.5 2173,-523.5 ; 3690,-730 3690,-526.67 ; 4280,-726.83 4280,-523.5 ; 4902,-1140 4902,-937.17
  text "ALL ARTWORK VIEWED FROM TOP SIDE" at -228.5,-655.67 h60
  text "BOARD #:" at 2248,-655.67 h60
  text "SVN REV:" at 4476,-655.67 h60
  text ".VersionControl_RevNumber" at 4982,-655.67 h60
  text "REV: E1" at 3785,-657 h60
  text "TIDA-00231" at 2720,-660 h60
  text "LAYER NAME =" at -228.5,-858.49 h60
  text "PLOT NAME =" at -228.5,-1064.34 h60
  text ".plot_File_Name" at 577,-1064.34 h60
  text "GENERATED    :" at 2250,-1064.34 h60
  text ".Print_Date" at 3119.5,-1064.34 h60
  text ".Print_Time" at 3848.5,-1064.34 h60
  text "TEXAS INSTRUMENTS" at 5113,-1064.34 h60
M12 Stackup:
  lines w5: 11335,7593.75 14215,7593.75 ; 11335,7688.95 14215,7688.95 ; 11275,6981 ccw(c11306,6981) 11306,6950 14244,6950 ccw(c14244,6981) 14275,6981 14275,7774 ccw(c14244,7774) 14244,7805 11306,7805 ccw(c11306,7774) 11275,7774 11275,6981
  text "Layer Stack Up Detail for: TIDA-00231.PcbDoc" at 11335,7714.27 h44
  text "Layer" at 11335,7653.45 h22
  text "Gerber" at 12335.83,7653.45 h22
  text "Copper" at 13036.82,7653.45 h22
  text "Dielectric" at 13773.74,7653.45 h22
  text "Name" at 11335,7609.45 h22
  text "Document" at 12335.83,7609.45 h22
  text "Thickness" at 13036.82,7609.45 h22
  text "Material" at 13773.74,7609.45 h22
  text "Top Solder Mask" at 11335,7546.72 h31
  text "(.GTS)" at 12335.83,7546.72 h31
  text "Solder Resist" at 13773.74,7546.72 h31
  text "Top Layer" at 11335,7457.66 h31
  text "(.GTL)" at 12335.83,7457.66 h31
  text "1.4mil" at 13036.82,7457.66 h31
  text "FR-4" at 13773.74,7413.13 h31
  text "L2_GND-PLANE" at 11335,7368.59 h31
  text "(.G1)" at 12335.83,7368.59 h31
  text "1.4mil" at 13036.82,7368.59 h31
  text "FR-4" at 13773.74,7324.06 h31
  text "L3_PWR-PLANE" at 11335,7279.53 h31
  text "(.G2)" at 12335.83,7279.53 h31
  text "1.4mil" at 13036.82,7279.53 h31
  text "FR-4" at 13773.74,7235 h31
  text "Bottom Layer" at 11335,7190.47 h31
  text "(.GBL)" at 12335.83,7190.47 h31
  text "1.4mil" at 13036.82,7190.47 h31
  text "Bottom Solder Mask" at 11335,7101.41 h31
  text "(.GBS)" at 12335.83,7101.41 h31
  text "Solder Resist" at 13773.74,7101.41 h31
M13 Component Bodies Top:
  text ".Layer_Name" at 577,-858.49 h60
M14 Component Bodies Bottom:
  text ".Layer_Name" at 577,-858.49 h60
M15 Courtyards Top:
  text ".Layer_Name" at 577,-858.49 h60
M16 Courtyards Bottom:
  text ".Layer_Name" at 577,-858.49 h60
Drill Drawing:
  text ".legend" at 4281.25,609.45 h60
  text "Drill Table" at 4280,455 h60
  text "FOR 12MIL DRILL +0/-12MIL" at 4332,319 h60
  text "FOR 16MIL DRILL +0/-16MIL" at 4340,209 h60
  text "FOR PTH DRILL +/-3MIL" at 4345,110 h60
  text "FOR NPTH DRILL +/-2MIL" at 4345,15 h60
  text ".Layer_Name" at 577,-858.49 h60

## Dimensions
0,2000 to 3780,2000 on Drill Drawing
3780,2000 to 3780,0 on Drill Drawing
